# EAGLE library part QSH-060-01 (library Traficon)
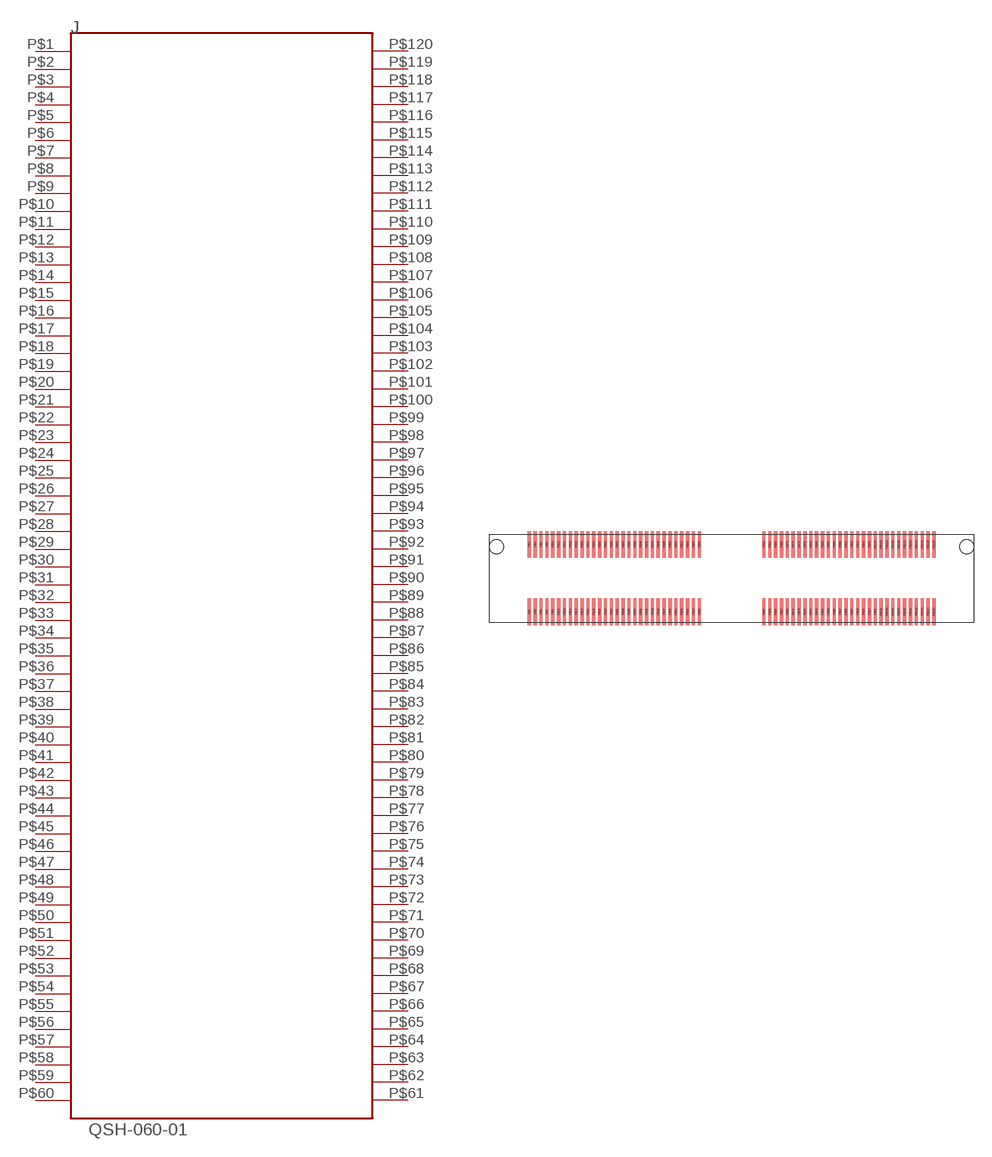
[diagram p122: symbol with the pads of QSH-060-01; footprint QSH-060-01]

Designator prefix J

## QSH-060-01  [QSH-060-01]
P$1  1
P$2  3
P$3  5
P$4  7
P$5  9
P$6  11
P$7  13
P$8  15
P$9  17
P$10  19
P$11  21
P$12  23
P$13  25
P$14  27
P$15  29
P$16  31
P$17  33
P$18  35
P$19  37
P$20  39
P$21  41
P$22  43
P$23  45
P$24  47
P$25  49
P$26  51
P$27  53
P$28  55
P$29  57
P$30  59
P$31  61
P$32  63
P$33  65
P$34  67
P$35  69
P$36  71
P$37  73
P$38  75
P$39  77
P$40  79
P$41  81
P$42  83
P$43  85
P$44  87
P$45  89
P$46  91
P$47  93
P$48  95
P$49  97
P$50  99
P$51  101
P$52  103
P$53  105
P$54  107
P$55  109
P$56  111
P$57  113
P$58  115
P$59  117
P$60  119
P$61  120
P$62  118
P$63  116
P$64  114
P$65  112
P$66  110
P$67  108
P$68  106
P$69  104
P$70  102
P$71  100
P$72  98
P$73  96
P$74  94
P$75  92
P$76  90
P$77  88
P$78  86
P$79  84
P$80  82
P$81  80
P$82  78
P$83  76
P$84  74
P$85  72
P$86  70
P$87  68
P$88  66
P$89  64
P$90  62
P$91  60
P$92  58
P$93  56
P$94  54
P$95  52
P$96  50
P$97  48
P$98  46
P$99  44
P$100  42
P$101  40
P$102  38
P$103  36
P$104  34
P$105  32
P$106  30
P$107  28
P$108  26
P$109  24
P$110  22
P$111  20
P$112  18
P$113  16
P$114  14
P$115  12
P$116  10
P$117  8
P$118  6
P$119  4
P$120  2

## Footprint QSH-060-01 (pad centres in mm)
smd 0.28 x 2.27: P$1 -17.255,-2.87; P$2 -17.255,2.87; P$3 -16.755,-2.87; P$4 -16.755,2.87; P$5 -16.255,-2.87; P$6 -16.255,2.87; P$7 -15.755,-2.87; P$8 -15.755,2.87; P$9 -15.255,-2.87; P$10 -15.255,2.87; P$11 -14.755,-2.87; P$12 -14.755,2.87; P$13 -14.255,-2.87; P$14 -14.255,2.87; P$15 -13.755,-2.87; P$16 -13.755,2.87; P$17 -13.255,-2.87; P$18 -13.255,2.87; P$19 -12.755,-2.87; P$20 -12.755,2.87; P$21 -12.255,-2.87; P$22 -12.255,2.87; P$23 -11.755,-2.87; P$24 -11.755,2.87; P$25 -11.255,-2.87; P$26 -11.255,2.87; P$27 -10.755,-2.87; P$28 -10.755,2.87; P$29 -10.255,-2.87; P$30 -10.255,2.87; P$31 -9.755,-2.87; P$32 -9.755,2.87; P$33 -9.255,-2.87; P$34 -9.255,2.87; P$35 -8.755,-2.87; P$36 -8.755,2.87; P$37 -8.255,-2.87; P$38 -8.255,2.87; P$39 -7.755,-2.87; P$40 -7.755,2.87; P$41 -7.255,-2.87; P$42 -7.255,2.87; P$43 -6.755,-2.87; P$44 -6.755,2.87; P$45 -6.255,-2.87; P$46 -6.255,2.87; P$47 -5.755,-2.87; P$48 -5.755,2.87; P$49 -5.255,-2.87; P$50 -5.255,2.87; P$51 -4.755,-2.87; P$52 -4.755,2.87; P$53 -4.255,-2.87; P$54 -4.255,2.87; P$55 -3.755,-2.87; P$56 -3.755,2.87; P$57 -3.255,-2.87; P$58 -3.255,2.87; P$59 -2.755,-2.87; P$60 -2.755,2.87; P$61 2.755,-2.87; P$62 2.755,2.87; P$63 3.255,-2.87; P$64 3.255,2.87; P$65 3.755,-2.87; P$66 3.755,2.87; P$67 4.255,-2.87; P$68 4.255,2.87; P$69 4.755,-2.87; P$70 4.755,2.87; P$71 5.255,-2.87; P$72 5.255,2.87; P$73 5.755,-2.87; P$74 5.755,2.87; P$75 6.255,-2.87; P$76 6.255,2.87; P$77 6.755,-2.87; P$78 6.755,2.87; P$79 7.255,-2.87; P$80 7.255,2.87; P$81 7.755,-2.87; P$82 7.755,2.87; P$83 8.255,-2.87; P$84 8.255,2.87; P$85 8.755,-2.87; P$86 8.755,2.87; P$87 9.255,-2.87; P$88 9.255,2.87; P$89 9.755,-2.87; P$90 9.755,2.87; P$91 10.255,-2.87; P$92 10.255,2.87; P$93 10.755,-2.87; P$94 10.755,2.87; P$95 11.255,-2.87; P$96 11.255,2.87; P$97 11.755,-2.87; P$98 11.755,2.87; P$99 12.255,-2.87; P$100 12.255,2.87; P$101 12.755,-2.87; P$102 12.755,2.87; P$103 13.255,-2.87; P$104 13.255,2.87; P$105 13.755,-2.87; P$106 13.755,2.87; P$107 14.255,-2.87; P$108 14.255,2.87; P$109 14.755,-2.87; P$110 14.755,2.87; P$111 15.255,-2.87; P$112 15.255,2.87; P$113 15.755,-2.87; P$114 15.755,2.87; P$115 16.255,-2.87; P$116 16.255,2.87; P$117 16.755,-2.87; P$118 16.755,2.87; P$119 17.255,-2.87; P$120 17.255,2.87
hole 1.2 at -20.065,2.67
hole 1.2 at 20.065,2.67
